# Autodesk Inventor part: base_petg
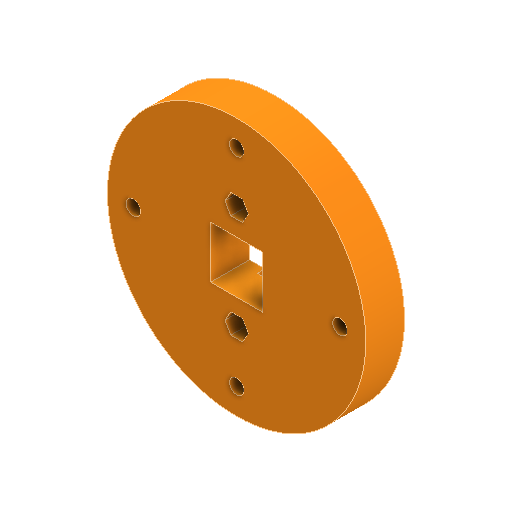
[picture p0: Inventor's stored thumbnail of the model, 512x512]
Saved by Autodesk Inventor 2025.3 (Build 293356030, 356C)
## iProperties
Created: 2025-09
Part Number: base_petg
Material: Plastica PET
Document SubType Name: Modeling
Designer: Ryzen5700u
Density: 1.541 g/cm^3
Appearance: Arancione
Author: Ryzen5700u
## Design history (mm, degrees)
sketch "Schizzo1"
  geometry: C1 r 50 at (0, 0); 1 further point
  constraints: 1 centre point, 1 coincident
  dimensions: "d0" = 100 diameter of C1
extrude "Estrusione1" new body sketch "Schizzo1" distance "d1" = 15; taper "d2" = 0 deg
sketch "Schizzo2"
  geometry: 2 further points
  dimensions: "d3" = 40 distance of point (0, 0) point (0, 40)
hole "Foro1" sketch "Schizzo2" at (0, 40) diameter "d4" = 5.5; stored, may be unused: countersink angle "d8" = 90 deg, drill point angle "d10" = 118 deg; dims "d5" = 6, "d6" = 9, "d7" = 4, "d9" = 8
pattern_circular "Serie circolare1" dims angle "d12" = 360 deg
sketch "Schizzo3"
  geometry: L1 (1.8, -17)-(-1.8, -17) reference; L2 (-1.8, 17)-(1.8, 17) reference; L3 (0, 17)-(0, 20); L4 (0, -17)-(0, -20); 3 further points
  constraints: 4 end point, 2 coincident, 2 point on line, 1 perpendicular, 1 vertical
  dimensions: "d14" = 3 distance of L3.start L3.end; "d15" = 3 distance of L4.start L4.end
hole "Foro2" sketch "Schizzo3" at (0, -20), (0, 20) diameter "d16" = 4.5; stored, may be unused: countersink angle "d20" = 90 deg, drill point angle "d22" = 118 deg; dims "d17" = 6, "d18" = 10, "d19" = 5.7, "d21" = 8
sketch "Schizzo4"
  geometry: L1 (-4.5, -20)-(-2.25, -16.103); L2 (-2.25, -16.103)-(2.25, -16.103); L3 (2.25, -16.103)-(4.5, -20); L4 (4.5, -20)-(2.25, -23.897); L5 (2.25, -23.897)-(-2.25, -23.897); L6 (-2.25, -23.897)-(-4.5, -20); L7 (-4.5, 20)-(-2.25, 23.897); L8 (-2.25, 23.897)-(2.25, 23.897); L9 (2.25, 23.897)-(4.5, 20); L10 (4.5, 20)-(2.25, 16.103); L11 (2.25, 16.103)-(-2.25, 16.103); L12 (-2.25, 16.103)-(-4.5, 20); C1 r 2.25 at (0, -20) reference; C2 r 2.25 at (0, 20) reference; 3 further points
  constraints: 24 end point, 2 coincident, 26 other
  dimensions: "d23" = 4.5 distance of L1.end L2.end; "d24" = 4.5 distance of L10.end L11.end
extrude "Estrusione2" cut sketch "Schizzo4" distance "d25" = 7; taper "d26" = 0 deg
sketch "Schizzo5"
  geometry: L1 (10.05, 10.05)-(-10.05, 10.05); L2 (-10.05, 10.05)-(-10.05, -10.05); L3 (-10.05, -10.05)-(10.05, -10.05); L4 (10.05, -10.05)-(10.05, 10.05); L5 (10.05, 10.05)-(-10.05, -10.05); L6 (-10.05, 10.05)-(10.05, -10.05); 1 further point
  constraints: 12 end point, 2 midpoint, 2 parallel, 1 horizontal, 1 perpendicular
  dimensions: "d27" = 20.1 distance of L3.end L2.end; "d28" = 20.1 distance of L2.end L1.end
extrude "Estrusione3" cut sketch "Schizzo5" extent not by distance; stored distance "d29" = 0; taper "d30" = 0 deg
sketch "Schizzo6"
  geometry: L1 (0, -2.636)-(0, -42.758); L2 (-4, -10.05)-(4, -10.05); L3 (4, -10.05)-(4, -28.05); L4 (4, -28.05)-(-4, -28.05); L5 (-4, -28.05)-(-4, -10.05); L6 (10.05, -10.05)-(-10.05, -10.05) reference; 2 further points
  constraints: 10 end point, 3 perpendicular, 2 midpoint, 1 other
  dimensions: "d33" = 8 distance of L3.end L4.end; "d34" = 18 distance of L2.end L3.end
extrude "Estrusione4" cut sketch "Schizzo6" distance "d31" = 3; taper "d32" = 0 deg
mirror "Speculare1"
node "Solido1"
node "Riferimento1"
node "Riferimento2"
